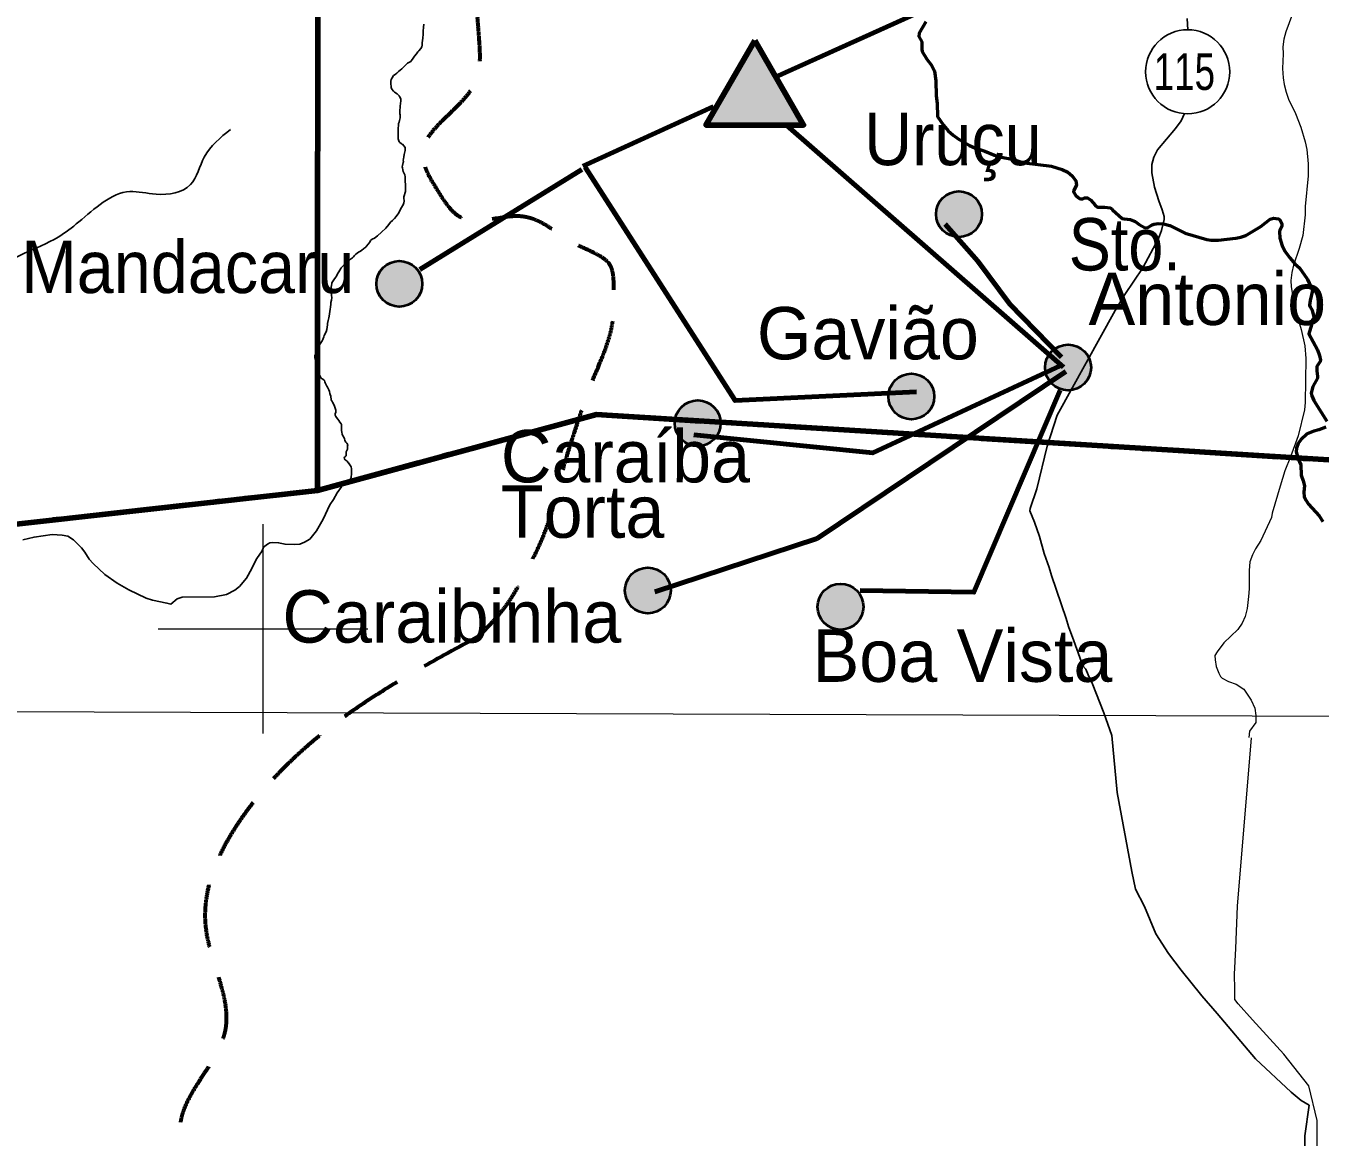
# Model space of a CAD drawing. Extents: x 553962 to 842807, y 8883888 to 9032388.
# Drawn here: x 747736 to 760090, y 8945147 to 8955756 of the extents above; entities that cross this region are included whole.
import ezdxf
from ezdxf.enums import TextEntityAlignment as Align

# ---------------------------------------------------------------- set-up
doc = ezdxf.new("R2010")
doc.units = 0
doc.header["$LTSCALE"] = 200
doc.linetypes.add('DASH_DOUBLE_DOT', pattern=[9.2, 5, -1.2, 0.3, -1.2, 0.3, -1.2])
doc.linetypes.add('MEDIUM_DASHED', pattern=[4.5, 3, -1.5])
for name, color, linetype, lineweight in [('1', 7, 'Continuous', 13), ('10', 7, 'MEDIUM_DASHED', 60), ('11', 7, 'DASH_DOUBLE_DOT', 106), ('12', 7, 'Continuous', 25), ('14', 7, 'Continuous', 13), ('2', 7, 'Continuous', 13), ('24', 7, 'Continuous', 25), ('28', 7, 'Continuous', 40), ('41', 7, 'Continuous', 40), ('48', 7, 'Continuous', 25), ('9', 7, 'Continuous', 90)]:
    doc.layers.add(name, color=color, linetype=linetype, lineweight=lineweight)

msp = doc.modelspace()

# ---------------------------------------------------------------- hatches: boundary and pattern name
at = {"layer": '28'}
msp.add_hatch(color=256, dxfattribs=at).paths.add_polyline_path([(754693.8, 8955615.2), (755160, 8954807.9), (754227.7, 8954807.9)])
at = {"layer": '41'}
for points in [[(756861, 8953958.3, 1), (756423.4, 8953958.3, 1)], [(751519.4, 8953293, 1), (751081.8, 8953293, 1)], [(757902.7, 8952494.5, 1), (757465.1, 8952494.5, 1)], [(756406.6, 8952217.3, 1), (755969, 8952217.3, 1)], [(754367.5, 8951962.3, 1), (753929.9, 8951962.3, 1)], [(753891, 8950365.4, 1), (753453.4, 8950365.4, 1)], [(755730.6, 8950210.1, 1), (755293, 8950210.1, 1)]]:
    msp.add_hatch(color=256, dxfattribs=at).paths.add_polyline_path(points)

# ---------------------------------------------------------------- linework, layer by layer
at = {"layer": '1'}
msp.add_line((565315.3, 8949866.8), (791497.7, 8949052.2), dxfattribs=at)
at = {"layer": '10'}
msp.add_open_spline([(752064, 8949931.3), (752226.2, 8950099), (752371.1, 8950281.5), (752484, 8950494.8), (752727.4, 8950954.4), (752832, 8951444.1), (752990, 8951926.7), (753136.7, 8952374.9), (753359.2, 8952845.2), (753347.9, 8953290.8), (753342, 8953522.6), (753008.5, 8953646.6), (752804.9, 8953784.5), (752471.5, 8954010.4), (751900.3, 8953804.2), (751669.5, 8954179.5), (751384.3, 8954643.3), (752099.3, 8955128.6), (752064.4, 8955611.4), (752024.1, 8956168.6), (751963.7, 8956738.7), (751718.9, 8957290.2)], degree=3, dxfattribs=at)
msp.add_spline([(752064, 8949931.3), (749882.4, 8948312.2), (749452.3, 8947143.5), (749636.6, 8946159.4), (749206.6, 8945236.7), (749452.3, 8944375.6), (748941.6, 8943614.3)], degree=3, dxfattribs=at)
at = {"layer": '11'}
for points in [[(750519.5, 8951321.2), (753181.6, 8952045.1), (767371, 8951165.8), (772338.7, 8947456.5)], [(737921.5, 8948812.5), (740981.3, 8950253.8), (750519.5, 8951321.2)]]:
    msp.add_lwpolyline(points, dxfattribs=at)
at = {"layer": '12'}
msp.add_line((757384.6, 8951334.8), (757323.5, 8951149.2), dxfattribs=at)
for points in [[(758821.1, 8955826.8), (758825.4, 8955718.1)], [(758795.3, 8954919.8), (758763.7, 8954849.6), (758709.9, 8954774.5), (758538.4, 8954573), (758503, 8954502.6), (758484, 8954433.8), (758484.1, 8954352.4), (758508.3, 8954214.7), (758549.7, 8954085.3), (758582.8, 8954000), (758600.3, 8953935.2), (758599.5, 8953906.9), (758576.1, 8953802), (758547.2, 8953725.3), (758396.4, 8953446.5), (758226.2, 8953190.3), (758132.7, 8953038)], [(758132.7, 8953038), (757580.3, 8952039.8), (757484.9, 8951743.2), (757384.6, 8951334.8)], [(757323.5, 8951149.2), (757320.3, 8951125.5), (757364.2, 8951016.5), (757410.7, 8950881), (757454.7, 8950719.9), (757502.3, 8950586.3), (757524.8, 8950509.5), (757666, 8950096.7), (757688, 8950021.8), (757738.6, 8949883.5)], [(757738.6, 8949883.5), (757825.6, 8949645.7), (757854.2, 8949615), (757875.3, 8949559.4), (757912.7, 8949482.2), (758025.8, 8949198.1), (758100.6, 8948982.2)], [(758100.6, 8948982.2), (758153.1, 8948438), (758293, 8947683.8), (758328, 8947515.6), (758414, 8947347.3), (758520, 8947087.3), (758641.6, 8946898.6), (758763.3, 8946740.5), (758961.1, 8946495.6), (759108.2, 8946327.2), (759473.4, 8945893.6), (759814, 8945575.9), (759907.3, 8945497.2), (759983.7, 8945452)], [(759983.7, 8945452), (759944.5, 8945159.2), (759944.1, 8945052.2), (759908, 8944950.4), (759862, 8944894.4), (759785, 8944751.9), (759708.2, 8944650.2), (759662.2, 8944609.5), (759602.9, 8944588), (759488.4, 8944585.1)]]:
    msp.add_lwpolyline(points, dxfattribs=at)
at = {"layer": '14'}
for points in [[(759858.6, 8955956.3), (759761.5, 8955697.4), (759741.8, 8955628.8), (759734.4, 8955555.9), (759735.8, 8955487.2), (759729.9, 8955349.5), (759736.2, 8955258.9), (759747.1, 8955195), (759765.6, 8955122.1), (759788.1, 8955057.4), (759856.1, 8954919.7), (759906.8, 8954790.2), (759947.4, 8954648.7), (759961.4, 8954575.8), (759976.4, 8954438.3), (759973.9, 8954322.7), (759947.5, 8954029.8), (759946, 8953952.7), (759923.2, 8953754.8), (759889.6, 8953629.9), (759834.2, 8953471.3), (759819.5, 8953402.5), (759811.3, 8953325.1), (759812.4, 8953265), (759848.2, 8953062.8), (759909.9, 8952856.4), (759942.4, 8952701.7), (759952.9, 8952580.2), (759946.5, 8952160.2), (759939.3, 8952091.6), (759880.8, 8951841.8), (759807.5, 8951640.4), (759753.1, 8951507.3), (759709.3, 8951360.8)], [(759709.3, 8951360.8), (759632, 8951102.5), (759624.2, 8951061.5), (759522.6, 8950843.3), (759474.2, 8950762.9), (759445.5, 8950706.2), (759419.9, 8950637.9), (759411.1, 8950557.2), (759411.4, 8950380.3), (759406.8, 8950307.6), (759392.1, 8950195), (759374.3, 8950118.4), (759344.4, 8950054), (759304, 8949993.2), (759170.9, 8949865.1), (759105.4, 8949780.7), (759086.2, 8949743.5), (759087.4, 8949705.1), (759098.4, 8949641.2), (759121.3, 8949577.4), (759137.2, 8949545.1), (759155.9, 8949527), (759216.2, 8949497.1), (759288.5, 8949470.6), (759360.2, 8949422), (759430.6, 8949317.8), (759467.5, 8949241.1), (759477.5, 8949172.3), (759475.1, 8949104), (759414.6, 8949021.4), (759409.5, 8948961.3)], [(760060.9, 8944960.3), (760062.2, 8945306.7), (759981.9, 8945637.9), (759743.6, 8945938.9), (759444.2, 8946265.5), (759307.2, 8946418.6), (759276.8, 8946459.4), (759277.1, 8946556.2), (759272.6, 8946703.9), (759283.7, 8946948.4), (759300.4, 8947350.8), (759434.4, 8948959.2)]]:
    msp.add_lwpolyline(points, dxfattribs=at)
at = {"layer": '2'}
for p, q in [((750000, 8949000), (750000, 8951000)), ((749000, 8950000), (751000, 8950000))]:
    msp.add_line(p, q, dxfattribs=at)
at = {"layer": '24'}
for points in [[(751533.5, 8955770.7), (751531.2, 8955742.9), (751527.4, 8955706), (751527.1, 8955688.9), (751529, 8955674), (751525.8, 8955639.9), (751521.3, 8955611.7), (751519.4, 8955598.1), (751518.8, 8955572), (751514.3, 8955556), (751506.3, 8955540.3), (751487.9, 8955518.6), (751476.7, 8955507.2), (751464.3, 8955487.1), (751446.1, 8955465), (751433, 8955446.6), (751417.1, 8955424.3), (751410.1, 8955416.6), (751379.8, 8955399.5), (751358.3, 8955381.5), (751341.1, 8955360.8), (751323.2, 8955344.1), (751293.9, 8955319.6), (751275.7, 8955305.3), (751259.5, 8955292.8), (751245.4, 8955280.6), (751231.7, 8955260.9), (751222.1, 8955244), (751218, 8955227.8), (751219.2, 8955211.1)], [(756324.5, 8955795.2), (756263.6, 8955684.9), (756259.8, 8955654.5), (756286.7, 8955604.2), (756288.2, 8955533), (756292.5, 8955510.1), (756334.1, 8955437.5), (756380.4, 8955379.2), (756407.6, 8955324), (756421.1, 8955229.4), (756423.2, 8955087.5), (756434.1, 8955015.4), (756438.6, 8954889.2), (756493.2, 8954806.4), (756538.7, 8954753.6), (756587.5, 8954711), (756633.8, 8954677.4), (756743.5, 8954615), (756793.6, 8954592.1), (756890.4, 8954560.2), (756980.7, 8954519.9), (757031, 8954506.2), (757164, 8954481.5), (757264.8, 8954446.9), (757524.6, 8954416.7), (757626.7, 8954382.9), (757679.9, 8954358.9), (757723, 8954324.3), (757758.4, 8954274.9), (757765.6, 8954237.9), (757739.5, 8954184.8), (757736.2, 8954171.3), (757757.5, 8954135.5), (757791.8, 8954108), (757806.3, 8954104.2), (757824.5, 8954106), (757844.9, 8954115.1), (757869, 8954113.3), (757902.6, 8954091.2), (757943.8, 8954043.1), (757966.1, 8954024.2), (758029.9, 8954025.6), (758085, 8954017.8), (758101.3, 8954008.5)], [(751219.2, 8955211.1), (751223.8, 8955165.8), (751229.9, 8955150.6), (751245.2, 8955131.5), (751254.7, 8955121.9), (751279.2, 8955106.3), (751297.5, 8955088.6), (751302.9, 8955080.6), (751310.3, 8955065.4), (751314.1, 8955055.2), (751314.7, 8955041.2), (751310.3, 8955015.7), (751307.7, 8954988.5), (751305.8, 8954937.9), (751306.7, 8954916), (751309.1, 8954905.5)], [(751309.1, 8954905.5), (751307.7, 8954878.1), (751301.9, 8954853), (751298.4, 8954837.1), (751293.7, 8954825), (751291.3, 8954811.7), (751288.5, 8954774.2), (751288.8, 8954720.4), (751288.8, 8954687.3), (751290.7, 8954677.2), (751300.6, 8954649.5), (751305.3, 8954642.5), (751318.4, 8954633.2), (751328.3, 8954627.8), (751332.1, 8954625.3)], [(751332.1, 8954625.3), (751355.9, 8954594), (751356.8, 8954581.6), (751355, 8954566), (751346.2, 8954527.5), (751344.9, 8954505.5), (751340.3, 8954487.1), (751337.9, 8954474.9), (751339.8, 8954461.6), (751337.9, 8954450.2), (751330.1, 8954423.6), (751328.8, 8954408.9), (751329.7, 8954399.3), (751334.7, 8954381.9), (751338, 8954365.6), (751347.6, 8954346.8), (751351.8, 8954334.4), (751355.4, 8954314.7), (751356.3, 8954289.5), (751358.6, 8954221.4), (751360.5, 8954199.8), (751358.2, 8954173.9), (751344.9, 8954124.4), (751343.9, 8954113), (751346.9, 8954083.7), (751343.8, 8954066), (751335.8, 8954047.5), (751314.9, 8954010.9), (751294.9, 8953971.7), (751270.3, 8953935.2), (751255.4, 8953915.8), (751235.4, 8953897.9), (751217.2, 8953882.7), (751198.8, 8953859.8), (751170.9, 8953825.3), (751131.4, 8953785.2), (751091.2, 8953752.8), (751063.4, 8953728), (751042, 8953718.8), (751024.7, 8953707.5)], [(758101.3, 8954008.5), (758106.9, 8953999.7), (758199.7, 8953917.6), (758218.4, 8953912.5), (758277.7, 8953907), (758325.5, 8953888.4), (758361.3, 8953858.8), (758419, 8953828.6), (758444.5, 8953830.4), (758487.6, 8953856), (758504.7, 8953862.3), (758544.9, 8953868.4), (758596.1, 8953866.1), (758654.8, 8953849.9), (758801, 8953777.3), (759008.6, 8953716.3), (759048.5, 8953710.9), (759118.3, 8953710.2), (759284.1, 8953730.2), (759331.6, 8953739.6), (759379.3, 8953754.1), (759522.6, 8953839.4), (759613.7, 8953910.2), (759644.3, 8953919), (759693.9, 8953913.5), (759706.3, 8953902.4), (759724.5, 8953867.6), (759724, 8953840.1), (759705.2, 8953806.7), (759701.8, 8953791.3), (759706.6, 8953728), (759727, 8953657.3), (759757.2, 8953601.2), (759799.2, 8953541), (759851.7, 8953481.5), (759893.5, 8953445.3), (759965.3, 8953342.1)], [(751024.7, 8953707.5), (751020.7, 8953696.5), (751014.4, 8953686.1), (751006.4, 8953674.5), (750985.2, 8953648.4)], [(750896.8, 8953584.2), (750886.7, 8953576), (750873.8, 8953563.7), (750863.4, 8953552.2), (750852.4, 8953541.5), (750833.6, 8953527.6), (750825.1, 8953520.3), (750818.7, 8953513.5), (750809.7, 8953502.3), (750797.1, 8953486.9), (750789.7, 8953478.8), (750777, 8953472.5), (750766.3, 8953466.8), (750757.3, 8953459.3), (750746.6, 8953446.4), (750741, 8953438.2), (750731.8, 8953423.6), (750723, 8953408.8), (750711.5, 8953388.1), (750700.2, 8953366.8), (750692.9, 8953354.2), (750675.2, 8953329.8), (750661.4, 8953311.1), (750656.3, 8953301.1), (750655, 8953296.7), (750651.6, 8953278.5), (750651.3, 8953261.4), (750650.2, 8953238.4), (750651.3, 8953219.6), (750653.3, 8953204.2), (750654.4, 8953182.6), (750655, 8953161.3), (750652.1, 8953137.2), (750647.9, 8953115.3), (750645.7, 8953100.4), (750643.2, 8953069.9), (750641.5, 8953049.7), (750633.6, 8953006.2), (750631.9, 8952984.9), (750628.5, 8952968.8), (750621.2, 8952943.5), (750616.2, 8952913.3), (750614.2, 8952902.7), (750612.8, 8952878.8), (750609.7, 8952855.8), (750602.6, 8952835.1), (750584.1, 8952800.1), (750578.5, 8952788.3), (750568.9, 8952760.9), (750564.4, 8952748), (750558.2, 8952739), (750552.9, 8952730.9), (750545.3, 8952719.9), (750536.8, 8952704.9), (750529.8, 8952688.7), (750523.1, 8952676.6), (750513.8, 8952662.3), (750506, 8952639.1), (750499.5, 8952623.1), (750495.6, 8952609.9), (750494.2, 8952597), (750494.2, 8952587.5), (750496.7, 8952581), (750498.4, 8952577.1), (750515, 8952523.4)], [(750986.8, 8953648.3), (750985.4, 8953646.6), (750979.8, 8953643), (750972.5, 8953637.9), (750963.2, 8953629.5), (750940.5, 8953610.7), (750922.4, 8953602.4), (750911.4, 8953595.1), (750896.8, 8953584.2)], [(759965.3, 8953342.1), (759970.4, 8953332.8), (760015.5, 8953230.4), (759993.3, 8953133.4), (759989.8, 8953090.2), (759995.2, 8953072.2), (760012.7, 8953041.9), (760030.5, 8952976.2), (760028.6, 8952967.7), (760010.5, 8952941.3), (760006.7, 8952900.2), (759980.5, 8952814.3), (760064.6, 8952661.4), (760083.7, 8952610.4), (760092.8, 8952563.5), (760088.5, 8952550.5), (760057.5, 8952502.3), (760057.1, 8952461.6), (760064.8, 8952411), (760063.1, 8952393.2), (760019.9, 8952313.4), (760004.7, 8952250.6), (760010.5, 8952223.1), (760028.2, 8952180.1), (760153.6, 8951982.2)], [(750515, 8952523.4), (750516.1, 8952514.7), (750516.4, 8952504.2), (750518.4, 8952485.1), (750519.2, 8952467.4), (750521.2, 8952458.4), (750526.2, 8952448.3), (750532.1, 8952434.9), (750535, 8952426.5), (750547.7, 8952403.8), (750555.5, 8952392.9), (750564.2, 8952385.3), (750580.2, 8952377.7), (750583.9, 8952374.9), (750585.9, 8952371.3), (750589, 8952358.9), (750592.7, 8952348.4), (750597.7, 8952335.7), (750609.2, 8952316.9), (750613.7, 8952307.1), (750626.7, 8952281), (750632.6, 8952265.7), (750637.1, 8952247.5), (750641, 8952237.3), (750645.2, 8952220.8)], [(750645.2, 8952220.8), (750650.6, 8952184.7), (750651.7, 8952177.7), (750656.5, 8952174.6), (750660.4, 8952170.1), (750663.8, 8952162), (750677.3, 8952136), (750689.4, 8952105.4), (750695.3, 8952086.9), (750695.3, 8952078.5), (750693, 8952066.5), (750687.7, 8952052), (750687.7, 8952040.5), (750693.9, 8952026.7), (750700.9, 8952015.8), (750713.9, 8951999.9), (750722.3, 8951988.1), (750733, 8951973.2), (750743.9, 8951957.8), (750747.3, 8951948.8), (750748.7, 8951932.1), (750748.1, 8951908.8), (750747, 8951893.1), (750751, 8951876.4), (750756.3, 8951858.5), (750761.9, 8951842.2), (750770.9, 8951828.7), (750777.7, 8951814.1), (750779.7, 8951800.5), (750783, 8951789.8), (750788.7, 8951782.5), (750799.9, 8951771.3), (750805.5, 8951762.6), (750807.5, 8951755.9), (750806.1, 8951746.1), (750804.6, 8951730.5), (750804.6, 8951720.1), (750805.5, 8951713.9), (750795.7, 8951694), (750793.1, 8951689.2), (750793.1, 8951685), (750794.2, 8951678.3), (750794.2, 8951671.6), (750792.6, 8951660.4), (750794.2, 8951655.1), (750793.7, 8951651.7), (750785, 8951644.2), (750776.3, 8951637.1), (750775.4, 8951629.6), (750776.6, 8951623.4), (750779.9, 8951616.9), (750784.4, 8951612.2), (750793.1, 8951606.6), (750801.1, 8951600.5), (750808.4, 8951589), (750812.6, 8951585.6), (750814.9, 8951584.1)], [(760142.6, 8951924.2), (760078.6, 8951897.8), (760029, 8951887.2), (759964.9, 8951861.7), (759906.3, 8951805.3), (759880.4, 8951769.2), (759863.6, 8951724.3), (759860.3, 8951690), (759879.4, 8951623.6), (759905.1, 8951565), (759908.9, 8951466.9), (759927.6, 8951412), (759938.9, 8951364.3), (759933.3, 8951303), (759936.8, 8951260.5), (759955, 8951224.7), (759979.8, 8951190.2), (760080.6, 8951077.7), (760114.7, 8951023.7)], [(750816.8, 8951585.2), (750841.2, 8951547.4), (750845.2, 8951526.5), (750845.3, 8951483.2), (750840.6, 8951445.4), (750835.5, 8951431.8), (750782.1, 8951389.9), (750747.8, 8951356.2), (750707.5, 8951297.9), (750673.1, 8951235.5), (750638.2, 8951183.6), (750572.6, 8951045), (750509.5, 8950935), (750444.8, 8950855.3), (750395, 8950825.3), (750352, 8950806.8), (750301.3, 8950803.8), (750210.4, 8950807.4), (750148.2, 8950821.9), (750091, 8950824.7), (750065.3, 8950821.8), (750040.7, 8950809.2), (750002.6, 8950778.6), (749989.8, 8950743.1), (749940.4, 8950671.8), (749917, 8950629.2), (749893.7, 8950575.8), (749841.7, 8950483.1), (749773.8, 8950404.3), (749730.5, 8950368.5), (749651.5, 8950328), (749536, 8950306.5), (749226.3, 8950300.4), (749179.3, 8950285.4), (749120.6, 8950234.1)], [(749120.6, 8950234.1), (749082.8, 8950244.7), (748944.7, 8950271.7), (748885.6, 8950293.6), (748719.8, 8950372.3), (748606.6, 8950436), (748490.4, 8950517), (748378, 8950622.7), (748339.6, 8950664), (748298.7, 8950730.8), (748267.4, 8950771.7), (748189.7, 8950850.3), (748135.7, 8950885.3), (748082.8, 8950893.4), (747987.7, 8950898.8), (747814.2, 8950875.3), (747707.5, 8950848.8)]]:
    msp.add_lwpolyline(points, dxfattribs=at)
at = {"layer": '24', "lineweight": 53}
for points in [[(756324.5, 8955795.2), (756263.6, 8955684.9), (756259.8, 8955654.5), (756286.7, 8955604.2), (756288.2, 8955533), (756292.5, 8955510.1), (756334.1, 8955437.5), (756380.4, 8955379.2), (756407.6, 8955324), (756421.1, 8955229.4), (756423.2, 8955087.5), (756434.1, 8955015.4), (756438.6, 8954889.2), (756493.2, 8954806.4), (756538.7, 8954753.6), (756587.5, 8954711), (756633.8, 8954677.4), (756743.5, 8954615), (756793.6, 8954592.1), (756890.4, 8954560.2), (756980.7, 8954519.9), (757031, 8954506.2), (757164, 8954481.5), (757264.8, 8954446.9), (757524.6, 8954416.7), (757626.7, 8954382.9), (757679.9, 8954358.9), (757723, 8954324.3), (757758.4, 8954274.9), (757765.6, 8954237.9), (757739.5, 8954184.8), (757736.2, 8954171.3), (757757.5, 8954135.5), (757791.8, 8954108), (757806.3, 8954104.2), (757824.5, 8954106), (757844.9, 8954115.1), (757869, 8954113.3), (757902.6, 8954091.2), (757943.8, 8954043.1), (757966.1, 8954024.2), (758029.9, 8954025.6), (758085, 8954017.8), (758101.3, 8954008.5)], [(758101.3, 8954008.5), (758106.9, 8953999.7), (758199.7, 8953917.6), (758218.4, 8953912.5), (758277.7, 8953907), (758325.5, 8953888.4), (758361.3, 8953858.8), (758419, 8953828.6), (758444.5, 8953830.4), (758487.6, 8953856), (758504.7, 8953862.3), (758544.9, 8953868.4), (758596.1, 8953866.1), (758654.8, 8953849.9), (758801, 8953777.3), (759008.6, 8953716.3), (759048.5, 8953710.9), (759118.3, 8953710.2), (759284.1, 8953730.2), (759331.6, 8953739.6), (759379.3, 8953754.1), (759522.6, 8953839.4), (759613.7, 8953910.2), (759644.3, 8953919), (759693.9, 8953913.5), (759706.3, 8953902.4), (759724.5, 8953867.6), (759724, 8953840.1), (759705.2, 8953806.7), (759701.8, 8953791.3), (759706.6, 8953728), (759727, 8953657.3), (759757.2, 8953601.2), (759799.2, 8953541), (759851.7, 8953481.5), (759893.5, 8953445.3), (759965.3, 8953342.1)], [(759965.3, 8953342.1), (759970.4, 8953332.8), (760015.5, 8953230.4), (759993.3, 8953133.4), (759989.8, 8953090.2), (759995.2, 8953072.2), (760012.7, 8953041.9), (760030.5, 8952976.2), (760028.6, 8952967.7), (760010.5, 8952941.3), (760006.7, 8952900.2), (759980.5, 8952814.3), (760064.6, 8952661.4), (760083.7, 8952610.4), (760092.8, 8952563.5), (760088.5, 8952550.5), (760057.5, 8952502.3), (760057.1, 8952461.6), (760064.8, 8952411), (760063.1, 8952393.2), (760019.9, 8952313.4), (760004.7, 8952250.6), (760010.5, 8952223.1), (760028.2, 8952180.1), (760153.6, 8951982.2)], [(760142.6, 8951924.2), (760078.6, 8951897.8), (760029, 8951887.2), (759964.9, 8951861.7), (759906.3, 8951805.3), (759880.4, 8951769.2), (759863.6, 8951724.3), (759860.3, 8951690), (759879.4, 8951623.6), (759905.1, 8951565), (759908.9, 8951466.9), (759927.6, 8951412), (759938.9, 8951364.3), (759933.3, 8951303), (759936.8, 8951260.5), (759955, 8951224.7), (759979.8, 8951190.2), (760080.6, 8951077.7), (760114.7, 8951023.7)]]:
    msp.add_lwpolyline(points, dxfattribs=at)
at = {"layer": '24'}
msp.add_spline([(746320.5, 8952725.9), (746386.2, 8952936.5), (746754.7, 8953055.1), (747110, 8953226.2), (747465.2, 8953450.1), (747715.3, 8953581.7), (748044.2, 8953739.7), (748241.6, 8953884.6), (748728.5, 8954174.2), (748978.5, 8954147.9), (749307.5, 8954240.1), (749439.1, 8954503.4), (749689.1, 8954766.8)], degree=3, dxfattribs=at)
at = {"layer": '28', "lineweight": 80}
for p, q in [((757134.6, 8956280.5), (754888.4, 8955266.6)), ((754300.7, 8954986.7), (753053.6, 8954417.3)), ((757641.4, 8952496.3), (755000.4, 8954804.2)), ((753042.6, 8954384.6), (751495.7, 8953430.6)), ((757660.9, 8952457.3), (755288.8, 8950861)), ((755288.8, 8950861), (753737.8, 8950354))]:
    msp.add_line(p, q, dxfattribs=at)
at = {"layer": '28', "lineweight": 90}
msp.add_lwpolyline([(754693.8, 8955615.2), (755160, 8954807.9), (754227.7, 8954807.9)], close=True, dxfattribs=at)
at = {"layer": '28', "lineweight": 80}
for points in [[(753075.4, 8954406.4), (754505, 8952178.7), (756237.8, 8952262.2)], [(756510.8, 8953861.8), (756822.7, 8953510.6), (757127.8, 8953099.3), (757621.9, 8952593.8)], [(757609.5, 8952510.3), (755819.7, 8951678.8), (754112.2, 8951852.4)], [(757608.4, 8952278), (756784.3, 8950347.9), (755697.8, 8950366.2)]]:
    msp.add_lwpolyline(points, dxfattribs=at)
at = {"layer": '41'}
for centre in [(756642.2, 8953958.3), (751300.6, 8953293), (757683.9, 8952494.5), (756187.8, 8952217.3), (754148.7, 8951962.3), (753672.2, 8950365.4), (755511.8, 8950210.1)]:
    msp.add_circle(centre, 218.8, dxfattribs=at)
at = {"layer": '48'}
msp.add_circle((758825.5, 8955317.1), 401.3, dxfattribs=at)
at = {"layer": '9'}
for points in [[(737921.5, 8948812.5), (740981.3, 8950253.8), (750519.5, 8951321.2), (750521.5, 8957798.6)], [(750519.5, 8951321.2), (753181.6, 8952045.1), (767371, 8951165.8), (772338.7, 8947456.5)]]:
    msp.add_lwpolyline(points, dxfattribs=at)

# ---------------------------------------------------------------- texts
at = {"layer": '41'}
for s, width, p in [('Uruçu', 0.95, (755737.2, 8954425.8)), ('Sto.', 0.9, (757690.2, 8953420.4)), ('Mandacaru', 0.95, (747692.5, 8953204.9))]:
    msp.add_text(s, height=500, dxfattribs=dict(at, width=width)).set_placement(p)
for s, p in [('Antonio', (757879.2, 8952900.3)), ('Gavião', (754713.8, 8952571.9)), ('Caraíba', (752269.6, 8951397.5)), ('Torta', (752269.6, 8950868.9)), ('Caraibinha', (750184.5, 8949867.8)), ('Boa Vista', (755244.8, 8949493.4))]:
    msp.add_text(s, height=500, dxfattribs=at).set_placement(p)
at = {"layer": '48', "width": 0.75}
msp.add_text('115', height=350, dxfattribs=at).set_placement((758793.9, 8955143.8), align=Align.CENTER)

doc.saveas('drawing.dxf')
